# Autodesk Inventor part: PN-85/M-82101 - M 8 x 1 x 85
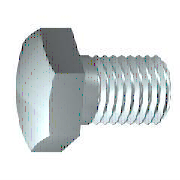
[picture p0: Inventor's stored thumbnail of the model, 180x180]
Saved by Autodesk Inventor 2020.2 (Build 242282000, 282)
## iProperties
Manager: www.cadconsulting.pl
Company: Fabian Stasiak CAD Consulting
Created: 2006-02
Part Number: PN-85/M-82101 - M 8 x 1 x 85
Material: Stal, miękka
Description: Śruba - A
Document SubType Name: Modeling
Standard: PN-85/M-82101
Designer: F.Stasiak
Standards Organization: PN
Language: pl-PL
Size Designation: M 8 x 1 x 85
Categories: <MemberInstance><Categories><Category DisplayName="Mocowania" InternalName="e4da775c-781d-43d5-af7c-5136215cf5a6" Mnemonic="FSTN"><Category DisplayName="Śruby"
Density: 1 g/cm^3
Appearance: Stal
Author: F.Stasiak
Subject: Zbiór ćwiczeń. Autodesk Inventor 2020. Kurs podstawowy
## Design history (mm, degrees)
sketch "Szkic1"
  geometry: L1 (0, 5.8)-(0, 4); L2 (63, 4)-(85, 4); L3 (85, 4)-(85, 0); L4 (85, 0)-(-0.6, 0); L5 (-9.16, 0)-(110.68, 0) reference; L6 (-0.6, 0)-(-0.6, 5.8); L7 (-0.6, 5.8)-(0, 5.8); L8 (63, 4)-(62.386, 4); L9 (62.386, 4)-(0, 4); L10 (0, -0.58)-(0, 7.54) reference
  constraints: 16 end point, 2 collinear, 2 perpendicular, 1 parallel
  dimensions: "d0" = 85 distance between parallel lines of L3 L1 (= NLG); "d1" = 22 distance from line of L2.start L3 (= GEL); "d2" = 8 diameter of L2 L4 (= GD); "d9" = 0.6001 distance between parallel lines of L6 L1 (computed from SD); "d10" = 11.6 diameter of L7 L4 (= SD2); "d13" = 0.61355 distance of L2.start L8.end (computed from GAL); "d14" = 8 diameter of L9 L4 (= BDM)
revolve "Bryła" sketch "Szkic1" stored, may be unused: angle "d12" = 90 deg
sketch "Szkic2"
  geometry: L1 (0, 7.506)-(6.5, 3.753); L2 (6.5, 3.753)-(6.5, -3.753); L3 (6.5, -3.753)-(0, -7.506); L4 (0, -7.506)-(-6.5, -3.753); L5 (-6.5, -3.753)-(-6.5, 3.753); L6 (-6.5, 3.753)-(0, 7.506); 2 further points
  constraints: 12 end point, 1 coincident, 1 vertical, 11 other
  dimensions: "d11" = 13 distance between parallel lines of L5 L2 (= SW)
extrude "Głowica" join sketch "Szkic2" distance "d3" = 4.7 (= KOH - SD); taper "d4" = 0 deg
sketch "Szkic4"
  geometry: L1 (-5.3, 6.5)-(-5.3, 7.506); L2 (-5.3, 7.506)-(-4.72, 7.506); L3 (-4.72, 7.506)-(-5.3, 6.5); L4 (-5.77, 0)-(0.81, 0) reference; L5 (-0.6, 7.506)-(-5.3, 7.506) reference; L6 (-5.3, 3.753)-(-5.3, 7.506) reference
  constraints: 6 end point, 2 collinear, 1 perpendicular, 1 vertical
  dimensions: "d5" = 30 deg angle of L3 L1 (= ANG1); "d19" = 13 diameter of L1.start L4 (= SW0)
revolve "Faza1" sketch "Szkic4" stored, may be unused: angle "d21" = 90 deg
workplane "Work Plane1"
node "Bryła1"
node "Korpusy bryłowe"
node "Korpusy powierzchniowe"
feature "Gwint" dims "d15" = 22 (= GEL), "d16" = 0
chamfer "Faza2" distance "d6" = 0.61345 (= -0.5 x SPD + 0.5 x GD); stored, may be unused: second distance "d7" = 0.61355 (computed from GUL), angle "d55" = 45 deg
other parameters: "NLG" = 85 [user parameter; used in 1 equation term], "GD" = 8 (= NND) [user parameter; used in 2 equation terms], "BDM" = 8 (= NND) [user parameter; used in 1 equation term], "KOH" = 5.3 [user parameter; used in 1 equation term], "GEL" = 22 [user parameter; used in 2 equation terms], "SW" = 13 [user parameter; used in 3 equation terms], "SW0" = 13 (= SW) [user parameter; used in 1 equation term], "SPD" = 6.7731 (= NND - 1.2269 x PTC) [user parameter; used in 1 equation term], "SD2" = 11.6 [user parameter; used in 1 equation term], "SD" = 0.6 [user parameter; used in 3 equation terms], "ANG1" = 30 deg [user parameter; used in 1 equation term], "GAL" = 0.61345 (= 0.61345 x PTC) [user parameter; used in 1 equation term], "GUL" = 0.61345 (= 0.61345 x PTC) [user parameter; used in 1 equation term], "d8" = 0, "RR" = 0.4 [user parameter], "d57" = 0, "d58" = 0, "WFT" = 0.6 (= SD) [user parameter], "GD1" = 6.7731 (= THREADDIA - 1.2269 x PTC) [user parameter], "THREADDIA" = 8 [user parameter; used in 1 equation term], "SDH" = 11.6 [user parameter], "TOA" = 30 deg [user parameter], "FAWI" = 45 deg [user parameter], "PTC" = 1 [user parameter; used in 5 equation terms], "NND" = 8 [user parameter; used in 3 equation terms], "E0" = 15.015 (= 1.155 x SW) [user parameter]
